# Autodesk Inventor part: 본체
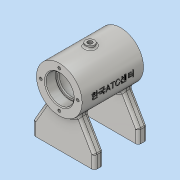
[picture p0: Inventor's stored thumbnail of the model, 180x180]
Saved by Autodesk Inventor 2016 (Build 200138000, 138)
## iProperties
Created: 2018-05
Part Number: 본체
Material: 알루미늄 6061
Document SubType Name: Modeling
Designer: 301-08
Density: 2.7 g/cm^3
Appearance: 알루미늄 - 평지
Mass: 317.681 g
Surface Area: 375.844 cm^2
Volume: 117.66 cm^3
Author: 301-08
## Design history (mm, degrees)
node "작업 평면1"
sketch "스케치1"
  geometry: 1 further point
sketch "스케치2"
  geometry: L1 (35, 0)-(-35, 0); L2 (35, 0)-(35, 15); L3 (35, 15)-(6.132, 65); L4 (6.132, 65)-(-6.132, 65); L5 (-6.132, 65)-(-35, 15); L6 (-35, 15)-(-35, 0); 2 further points
  constraints: 12 end point, 1 coincident, 1 horizontal, 1 midpoint, 1 parallel, 1 perpendicular, 1 vertical
  dimensions: "d1" = 70 distance of L1.start L1.end; "d2" = 15 distance of L1.start L2.end; "d3" = 15 distance of L5.end L1.end; "d4" = 30 deg angle of L2 L3; "d5" = 30 deg angle of L6 L5; "d6" = 65 distance between parallel lines of L1 L4
extrude "돌출1" new body sketch "스케치2" distance "d7" = 10; taper "d8" = 0 deg
sketch "스케치3"
  geometry: L1 (-35, 65)-(35, 65); L2 (0, 0)-(0, 29.935); L3 (-35, 65)-(-35, 91); L4 (-35, 91)-(35, 91); L5 (35, 91)-(35, 65); 1 further point
  constraints: 10 end point, 2 perpendicular, 2 vertical, 1 horizontal, 1 midpoint, 1 point on line
  dimensions: "d9" = 70 distance of L1.start L1.end; "d10" = 65 distance from line of L2.start L1; "d11" = 52 diameter of L4 L1
revolve "회전1" sketch "스케치3" stored, may be unused: angle "d12" = 90 deg
sketch "스케치4"
  geometry: L1 (-35, 39)-(-35, 91) reference; L2 (-35, 65)-(35, 65); L3 (35, 39)-(35, 91) reference; L4 (-35, 65)-(-35, 81); L5 (-35, 81)-(-23, 81); L6 (-23, 81)-(-23, 79); L7 (-23, 79)-(-21, 79); L8 (-21, 79)-(-21, 86); L9 (-21, 86)-(21, 86); L10 (21, 86)-(21, 79); L11 (21, 79)-(23, 79); L12 (23, 79)-(23, 81); L13 (23, 81)-(35, 81); L14 (35, 81)-(35, 65); 1 further point
  constraints: 24 end point, 8 perpendicular, 2 midpoint, 2 point on line, 1 collinear, 1 horizontal
  dimensions: "d13" = 65 distance from line of point (0, 0) L2 (derived); "d14" = 32 diameter of L5 L2; "d15" = 28 diameter of L7 L2; "d16" = 42 diameter of L9 L2; "d17" = 12 distance of L4.end L5.end; "d18" = 2 distance of L6.end L7.end; "d19" = 42 distance of L8.end L9.end; "d20" = 2 distance of L10.end L11.end; "d21" = 12 distance of L12.end L13.end (derived); "d22" = 32 diameter of L13 L2; "d23" = 28 diameter of L11 L2
revolve "회전2" sketch "스케치4" stored, may be unused: angle "d24" = 90 deg
node "작업 평면2"
sketch "스케치5"
  geometry: L1 (26, -35)-(-26, -35) reference; C1 r 5 at (0, 0); 1 further point
  constraints: 1 centre point, 1 coincident
  dimensions: "d26" = 10 diameter of C1; "d27" = 35 distance from line of L1 C1.centre (derived)
extrude "돌출2" join sketch "스케치5" stored distance "d28" = 10; taper "d29" = 0 deg
sketch "스케치6"
  geometry: L1 (0, 65)-(17.273, 17.542); L2 (17.273, 17.542)-(0, 65); L3 (0, 0)-(0, 65); L4 (35, 0)-(-35, 0) reference; 1 further point
  constraints: 6 end point, 1 collinear, 1 perpendicular, 1 point on line, 2 other
  dimensions: "d30" = 20 deg angle of L3 L1
node "작업 평면3"
sketch "스케치7"
  geometry: C1 r 6 at (0, 0); 2 further points
  constraints: 1 centre point, 1 coincident, 1 other
  dimensions: "d31" = 12 diameter of C1
extrude "돌출3" join sketch "스케치7" stored distance "d32" = 6; taper "d33" = 0 deg
hole "구멍1" diameter "d36" = 5.188; stored, may be unused: countersink angle "d40" = 90 deg, drill point angle "d42" = 118 deg; dims "d34" = 10, "d35" = 10, "d37" = 12, "d38" = 4, "d39" = 2, "d41" = 16
hole "구멍2" diameter "d45" = 5.188; stored, may be unused: countersink angle "d49" = 90 deg, drill point angle "d51" = 118 deg; dims "d43" = 10, "d44" = 10, "d46" = 12, "d47" = 4, "d48" = 2, "d50" = 16
fillet "모깎기1" dims "d52" = 2
sketch "스케치8"
  geometry: L1 (0, 21)-(0, 0); C1 r 21 at (0, 0) reference; 2 further points
  constraints: 2 end point, 1 vertical, 1 other
  dimensions: "d53" = 21 distance of point (0, 0) L1.start
hole "구멍3" sketch "스케치8" at (0, 21) diameter "d54" = 3.242; stored, may be unused: countersink angle "d58" = 90 deg, drill point angle "d60" = 118 deg; dims "d55" = 8, "d56" = 4, "d57" = 2, "d59" = 10
sketch "스케치9"
  geometry: 1 further point
sketch "스케치10"
  geometry: 2 further points
  dimensions: "d64" = 25 vertical distance of point (20, -25) point (0, 0); "d65" = 20 horizontal distance of point (0, 0) point (20, -25)
hole "구멍4" sketch "스케치10" at (20, -25) diameter "d66" = 4.134; stored, may be unused: countersink angle "d70" = 90 deg, drill point angle "d72" = 118 deg; dims "d67" = 8, "d68" = 4, "d69" = 2, "d71" = 10
node "작업 평면4"
sketch "스케치11"
  geometry: L1 (-35, -26)-(-35, 26) reference; L2 (-35, 26)-(35, 26) reference; 2 further points
  constraints: 1 other
  dimensions: "d79" = 35 distance from line of L1 point (0, 0); "d80" = 26 distance from line of point (0, 0) L2
feature "엠보싱1" sketch "스케치11" dims "d1" = 70, "d2" = 15, "d3" = 15, "d4" = 30 deg, "d5" = 30 deg, "d6" = 65, "d81" = 0.5, "d82" = 0
fillet "모깎기2" dims "d83" = 3
chamfer "모따기1" distance "d84" = 1; stored, may be unused: second distance "d85" = 2, angle "d86" = 45 deg
fillet "모깎기3" dims "d87" = 3
fillet "모깎기4" dims "d88" = 0.3
sketch "스케치12"
  geometry: L1 (0, 103.656)-(-52.165, 103.656); L2 (-52.165, 103.656)-(-52.165, -10.938); L3 (-52.165, -10.938)-(0, -10.938); L4 (0, -10.938)-(0, 103.656); 1 further point
  constraints: 8 end point, 2 parallel, 1 horizontal, 1 perpendicular
extrude "돌출4" cut sketch "스케치12" stored distance "d89" = 0; taper "d90" = 0 deg
node "솔리드1"
mirror "대칭1"
pattern_circular "원형 패턴1" dims angle "d62" = 360 deg
mirror "대칭2"
pattern_linear "직사각형 패턴1" dims "d75" = 40
other parameters: "d25" = 94
